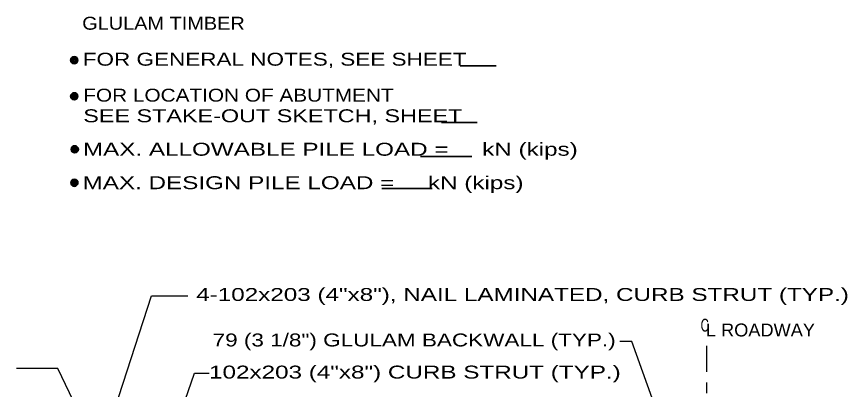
# Model space of a CAD drawing. Extents: x -6.4 to 73.1, y -66 to 0.
# Drawn here: x 7.44 to 15.14, y -14.42 to -10.96 of the extents above; entities that cross this region are included whole.
import ezdxf
from ezdxf.enums import TextEntityAlignment as Align

# ---------------------------------------------------------------- set-up
doc = ezdxf.new("R2010")
doc.units = 0
doc.header["$LTSCALE"] = 0.048
doc.linetypes.add('DOT_DASHED', pattern=[7.7, 5, -1.2, 0.3, -1.2])
doc.layers.add('5', color=7, linetype='Continuous', lineweight=25)

msp = doc.modelspace()

# ---------------------------------------------------------------- linework, layer by layer
at = {"layer": '5', "lineweight": 35}
for p, q in [((11.55183, -11.41608), (11.88375, -11.41608)), ((11.37725, -11.94017), (11.70917, -11.94017)), ((11.18383, -12.25642), (11.658, -12.25642)), ((10.82525, -12.55383), (11.29, -12.55383))]:
    msp.add_line(p, q, dxfattribs=at)
at = {"layer": '5'}
for p, q in [((8.09567, -15.38017), (8.69033, -13.55058)), ((8.69033, -13.55058), (9.02467, -13.55058)), ((7.82083, -14.22442), (7.43817, -14.22442)), ((8.06058, -14.72783), (7.82075, -14.22442)), ((8.70217, -15.38017), (9.08692, -14.26717)), ((9.08692, -14.26717), (9.22317, -14.26717))]:
    msp.add_line(p, q, dxfattribs=at)
at = {"layer": '5', "linetype": 'DOT_DASHED'}
msp.add_line((13.83458, -14.01525), (13.83458, -15.07467), dxfattribs=at)
at = {"layer": '5'}
msp.add_lwpolyline([(13.47725, -14.905), (13.1435, -13.97367), (13.03008, -13.97367)], dxfattribs=at)
at = {"layer": '5', "lineweight": 35}
for centre, radius in [((7.97232, -11.36275), 0.03333), ((7.97232, -11.36275), 0.025), ((7.97232, -11.36275), 0.01667), ((7.97232, -11.36275), 0.00833), ((7.97232, -11.69767), 0.03333), ((7.97232, -11.69767), 0.025), ((7.97232, -11.69767), 0.01667), ((7.97232, -11.69767), 0.00833), ((7.97731, -12.19007), 0.03333), ((7.97731, -12.19007), 0.025), ((7.97731, -12.19007), 0.01667), ((7.97731, -12.19007), 0.00833), ((7.97393, -12.50079), 0.03333), ((7.97393, -12.50079), 0.025), ((7.97393, -12.50079), 0.01667), ((7.97393, -12.50079), 0.00833)]:
    msp.add_circle(centre, radius, dxfattribs=at)

# ---------------------------------------------------------------- texts
at = {"layer": '5'}
for s, width, p in [('GLULAM TIMBER', 1.15, (8.04642, -11.07975)), ('FOR GENERAL NOTES, SEE SHEET    ', 1.3, (8.05142, -11.41367)), ('FOR LOCATION OF ABUTMENT', 1.2, (8.05642, -11.74758)), ('SEE STAKE-OUT SKETCH, SHEET    ', 1.35, (8.05642, -11.93883)), ('MAX. ALLOWABLE PILE LOAD =     kN (kips)', 1.4, (8.05308, -12.24958)), ('MAX. DESIGN PILE LOAD =     kN (kips)', 1.4, (8.04967, -12.56025)), ('4-102x203 (4"x8"), NAIL LAMINATED, CURB STRUT (TYP.)', 1.4, (9.10333, -13.59808)), ('79 (3 1/8") GLULAM BACKWALL (TYP.)', 1.3, (9.25558, -14.02042)), ('102x203 (4"x8") CURB STRUT (TYP.)', 1.4, (9.2225, -14.3185))]:
    msp.add_text(s, height=0.12, dxfattribs=dict(at, width=width)).set_placement(p)
for s, width, p in [('C', 0.65, (13.81875, -13.88325)), ('L ROADWAY', 1.05, (14.33512, -13.92767))]:
    msp.add_text(s, height=0.12, dxfattribs=dict(at, width=width)).set_placement(p, align=Align.CENTER)

doc.saveas('drawing.dxf')
